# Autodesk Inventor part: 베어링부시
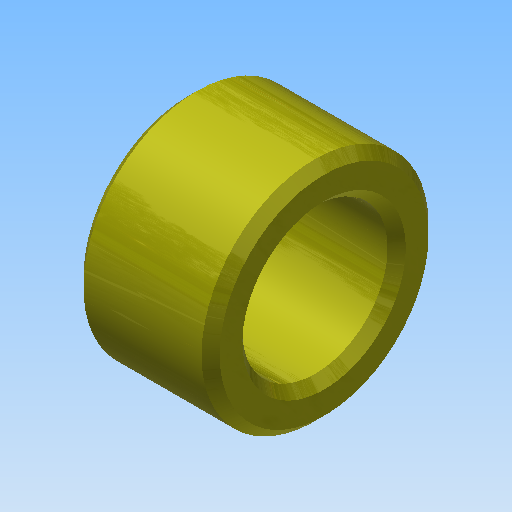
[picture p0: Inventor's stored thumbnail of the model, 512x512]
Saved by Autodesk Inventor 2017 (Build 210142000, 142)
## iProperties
Created: 2019-03
Part Number: 베어링부시
Material: 강철, 연강
Document SubType Name: Modeling
Designer: mduedu
Density: 1 g/cm^3
Appearance: 노란색
Author: mduedu
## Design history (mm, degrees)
sketch "스케치1"
  geometry: L1 (-7.5, 12.5)-(7.5, 12.5); L2 (7.5, 12.5)-(7.5, 8); L3 (7.5, 8)-(-7.5, 8); L4 (-7.5, 8)-(-7.5, 12.5); L5 (-7.5, 0)-(7.5, 0); 3 further points
  constraints: 10 end point, 2 midpoint, 2 parallel, 2 perpendicular, 2 vertical alignment, 1 coincident, 1 horizontal
  dimensions: "d0" = 16 diameter of L3 L5; "d2" = 25 diameter of L1 L5; "d3" = 15 distance of L1.start L1.end
revolve "회전1" sketch "스케치1" stored, may be unused: angle "d4" = 90 deg
chamfer "모따기1" distance "d5" = 1; stored, may be unused: second distance "d6" = 2, angle "d7" = 45 deg
chamfer "모따기2" distance "d8" = 1; stored, may be unused: second distance "d9" = 2, angle "d10" = 45 deg
node "솔리드1"
